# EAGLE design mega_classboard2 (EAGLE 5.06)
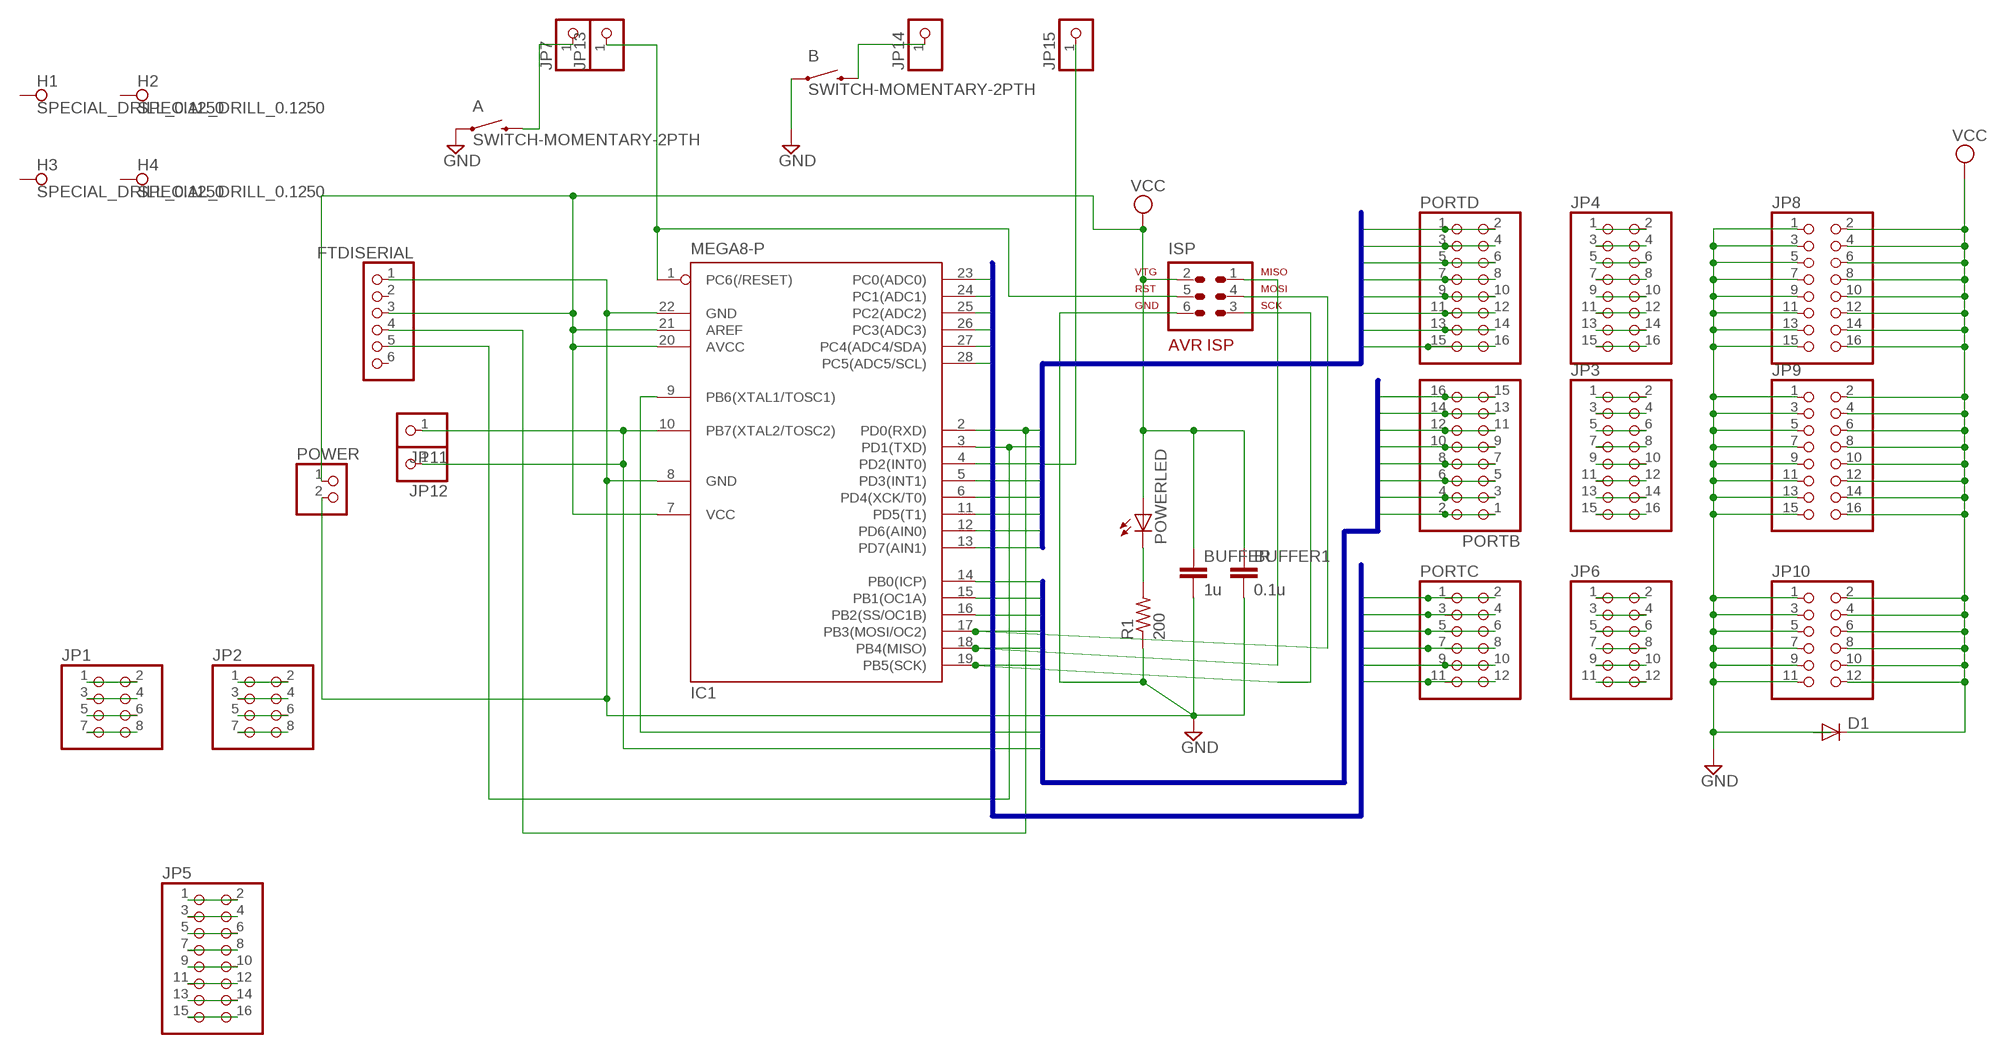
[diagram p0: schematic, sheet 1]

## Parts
A  SWITCH-MOMENTARY-2PTH  [TACTILE-PTH]
B  SWITCH-MOMENTARY-2PTH  [TACTILE-PTH]
BUFFER  1u  C5/3.5  [C5B3.5]
BUFFER1  0.1u  C5/3.5  [C5B3.5]
D1  DIODE1N4148  [DIODE-1N4148]
FTDISERIAL  PINHD-1X6  [1X06]
H1  SPECIAL_DRILL_0.1250  [PAD_0.1250]
H2  SPECIAL_DRILL_0.1250  [PAD_0.1250]
H3  SPECIAL_DRILL_0.1250  [PAD_0.1250]
H4  SPECIAL_DRILL_0.1250  [PAD_0.1250]
IC1  MEGA8-P  [DIL28-3]
ISP  AVR-ISP-6  [AVR-ISP-6]
JP1  PINHD-2X4  [2X04]
JP2  PINHD-2X4  [2X04]
JP3  PINHD-2X8  [2X08]
JP4  PINHD-2X8  [2X08]
JP5  PINHD-2X8  [2X08]
JP6  PINHD-2X6  [2X06]
JP7  PINHD-1X1  [1X01]
JP8  PINHD-2X8  [2X08]
JP9  PINHD-2X8  [2X08]
JP10  PINHD-2X6  [2X06]
JP11  PINHD-1X1  [1X01]
JP12  PINHD-1X1  [1X01]
JP13  PINHD-1X1  [1X01]
JP14  PINHD-1X1  [1X01]
JP15  PINHD-1X1  [1X01]
PORTB  PINHD-2X8  [2X08]
PORTC  PINHD-2X6  [2X06]
PORTD  PINHD-2X8  [2X08]
POWER  PINHD-1X2  [1X02]
POWERLED  LED5MM  [LED5MM]
R1  200  R-US_0204/7  [0204/7]

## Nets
GND: A.1 B.1 BUFFER1.2 BUFFER.2 FTDISERIAL.1 IC1.8(GND) IC1.22(GND) ISP.6 JP8.1 JP8.3 JP8.5 JP8.7 JP8.9 JP8.11 JP8.13 JP8.15 JP9.1 JP9.3 JP9.5 JP9.7 JP9.9 JP9.11 JP9.13 JP9.15 JP10.1 JP10.3 JP10.5 JP10.7 JP10.9 JP10.11 POWER.2 R1.1
N$1: POWERLED.K(C) R1.2
N$2: IC1.1(PC6(/RESET)) ISP.5 JP13.1
N$3: JP6.11 JP6.12
N$4: JP6.9 JP6.10
N$5: JP6.7 JP6.8
N$6: JP6.5 JP6.6
N$7: JP6.3 JP6.4
N$8: JP6.1 JP6.2
N$9: JP3.15 JP3.16
N$10: JP3.13 JP3.14
N$11: JP3.11 JP3.12
N$12: JP3.9 JP3.10
N$13: JP3.7 JP3.8
N$14: JP3.5 JP3.6
N$15: JP3.3 JP3.4
N$16: JP3.1 JP3.2
N$17: JP4.15 JP4.16
N$18: JP4.13 JP4.14
N$19: JP4.11 JP4.12
N$20: JP4.9 JP4.10
N$21: JP4.7 JP4.8
N$22: JP4.5 JP4.6
N$23: JP4.3 JP4.4
N$24: JP4.1 JP4.2
N$25: JP1.1 JP1.2
N$26: JP1.3 JP1.4
N$27: JP1.5 JP1.6
N$28: JP1.7 JP1.8
N$29: JP2.1 JP2.2
N$30: JP2.3 JP2.4
N$31: JP2.5 JP2.6
N$32: JP2.7 JP2.8
N$33: JP5.1 JP5.2
N$34: JP5.3 JP5.4
N$35: JP5.5 JP5.6
N$36: JP5.7 JP5.8
N$37: JP5.9 JP5.10
N$38: JP5.11 JP5.12
N$39: JP5.13 JP5.14
N$40: JP5.15 JP5.16
N$41: B.3 JP14.1
N$46: A.3 JP7.1
PORTB0: IC1.14(PB0(ICP)) PORTB.1 PORTB.2
PORTB1: IC1.15(PB1(OC1A)) PORTB.3 PORTB.4
PORTB2: IC1.16(PB2(SS/OC1B)) PORTB.5 PORTB.6
PORTB3: IC1.17(PB3(MOSI/OC2)) ISP.4 PORTB.7 PORTB.8
PORTB4: IC1.18(PB4(MISO)) ISP.1 PORTB.9 PORTB.10
PORTB5: IC1.19(PB5(SCK)) ISP.3 PORTB.11 PORTB.12
PORTB6: IC1.9(PB6(XTAL1/TOSC1)) PORTB.13 PORTB.14
PORTB7: IC1.10(PB7(XTAL2/TOSC2)) JP11.1 JP12.1 PORTB.15 PORTB.16
PORTC0: IC1.23(PC0(ADC0)) PORTC.1 PORTC.2
PORTC1: IC1.24(PC1(ADC1)) PORTC.3 PORTC.4
PORTC2: IC1.25(PC2(ADC2)) PORTC.5 PORTC.6
PORTC3: IC1.26(PC3(ADC3)) PORTC.7 PORTC.8
PORTC4: IC1.27(PC4(ADC4/SDA)) PORTC.9 PORTC.10
PORTC5: IC1.28(PC5(ADC5/SCL)) PORTC.11 PORTC.12
PORTD0: FTDISERIAL.4 IC1.2(PD0(RXD)) PORTD.1 PORTD.2
PORTD1: FTDISERIAL.5 IC1.3(PD1(TXD)) PORTD.3 PORTD.4
PORTD2: IC1.4(PD2(INT0)) JP15.1 PORTD.5 PORTD.6
PORTD3: IC1.5(PD3(INT1)) PORTD.7 PORTD.8
PORTD4: IC1.6(PD4(XCK/T0)) PORTD.9 PORTD.10
PORTD5: IC1.11(PD5(T1)) PORTD.11 PORTD.12
PORTD6: IC1.12(PD6(AIN0)) PORTD.13 PORTD.14
PORTD7: IC1.13(PD7(AIN1)) PORTD.15 PORTD.16
VCC: BUFFER1.1 BUFFER.1 D1.C FTDISERIAL.3 IC1.7(VCC) IC1.20(AVCC) IC1.21(AREF) ISP.2 JP8.2 JP8.4 JP8.6 JP8.8 JP8.10 JP8.12 JP8.14 JP8.16 JP9.2 JP9.4 JP9.6 JP9.8 JP9.10 JP9.12 JP9.14 JP9.16 JP10.2 JP10.4 JP10.6 JP10.8 JP10.10 JP10.12 POWER.1 POWERLED.A
Unconnected: D1.A FTDISERIAL.2 FTDISERIAL.6 H1.1 H2.1 H3.1 H4.1

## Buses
PORTD[0..7]
PORTB[0..7]
PORTC[0..5]

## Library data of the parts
A B = SparkFun:SWITCH-MOMENTARY-2
BUFFER BUFFER1 = capacitor-wima:C: CAPACITOR
D1 = SparkFun:DIODE: Diode
FTDISERIAL = pinhead:PINHD-1X6: PIN HEADER
H1-H4 = special-drill:SPECIAL_DRILL_: Special drills
IC1 = atmel:MEGA8-P: MICROCONTROLLER 8 Kbytes FLASH, 1 kbytes SRAM, 512 bytes EEPROM, USART, 4-channel 10 bit ADC, 2-channel 8 bit ADC Pin compatible with Atmega48, ATMega88, ATMega168 Source: avr.lbr
ISP = atmel-1:AVR-ISP-6: AVR ISP-6 Serial Programming Header
JP1 JP2 = pinhead:PINHD-2X4: PIN HEADER
JP3-JP5 JP8 JP9 PORTB PORTD = pinhead:PINHD-2X8: PIN HEADER
JP6 JP10 PORTC = pinhead:PINHD-2X6: PIN HEADER
JP7 JP11-JP15 = pinhead:PINHD-1X1: PIN HEADER
POWER = pinhead:PINHD-1X2: PIN HEADER
POWERLED = led:LED: LED
R1 = rcl:R-US_: RESISTOR, American symbol

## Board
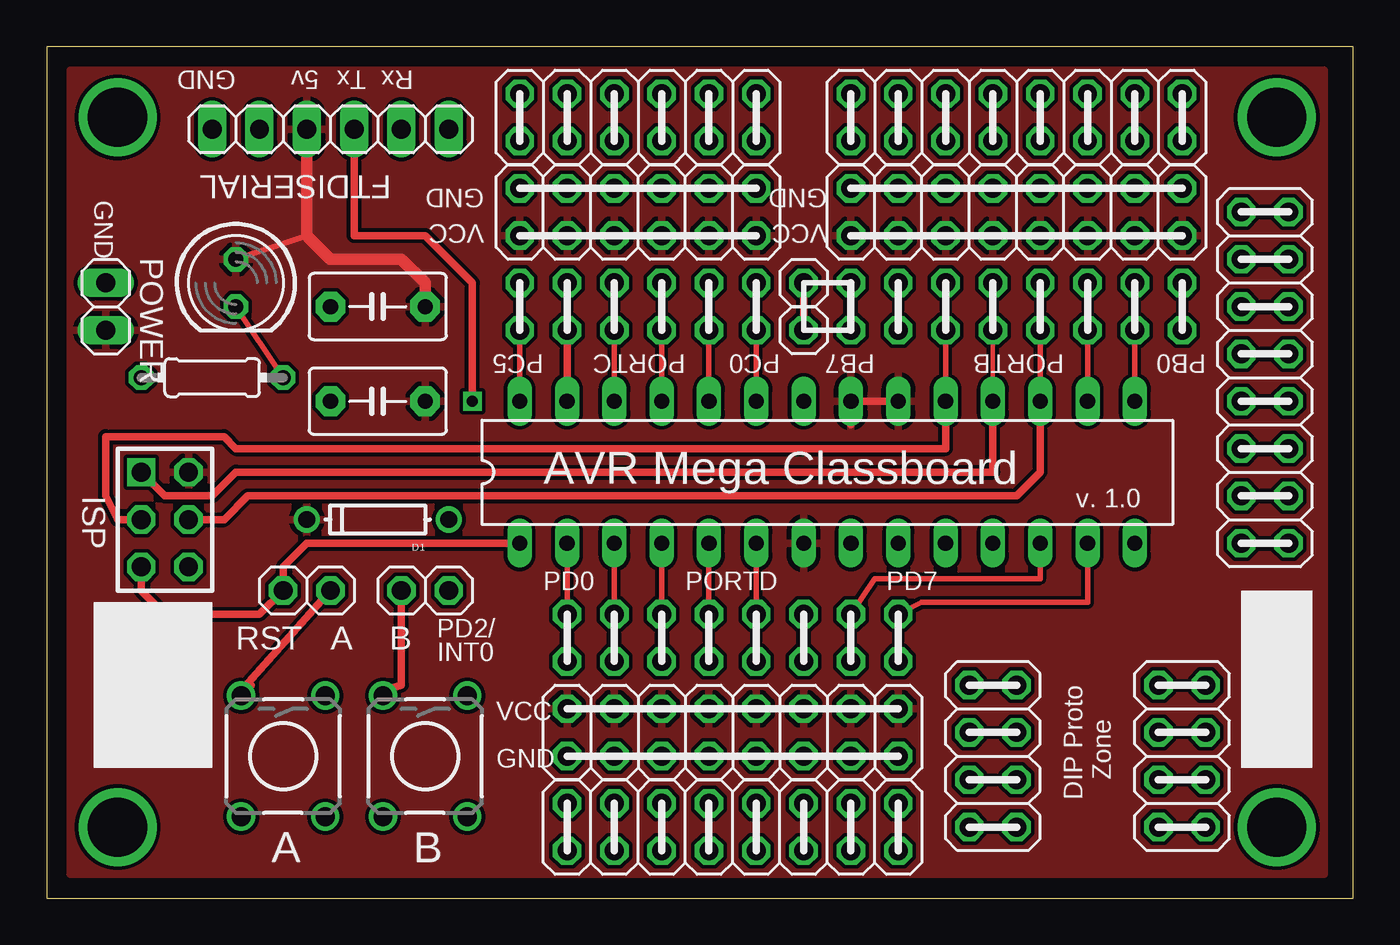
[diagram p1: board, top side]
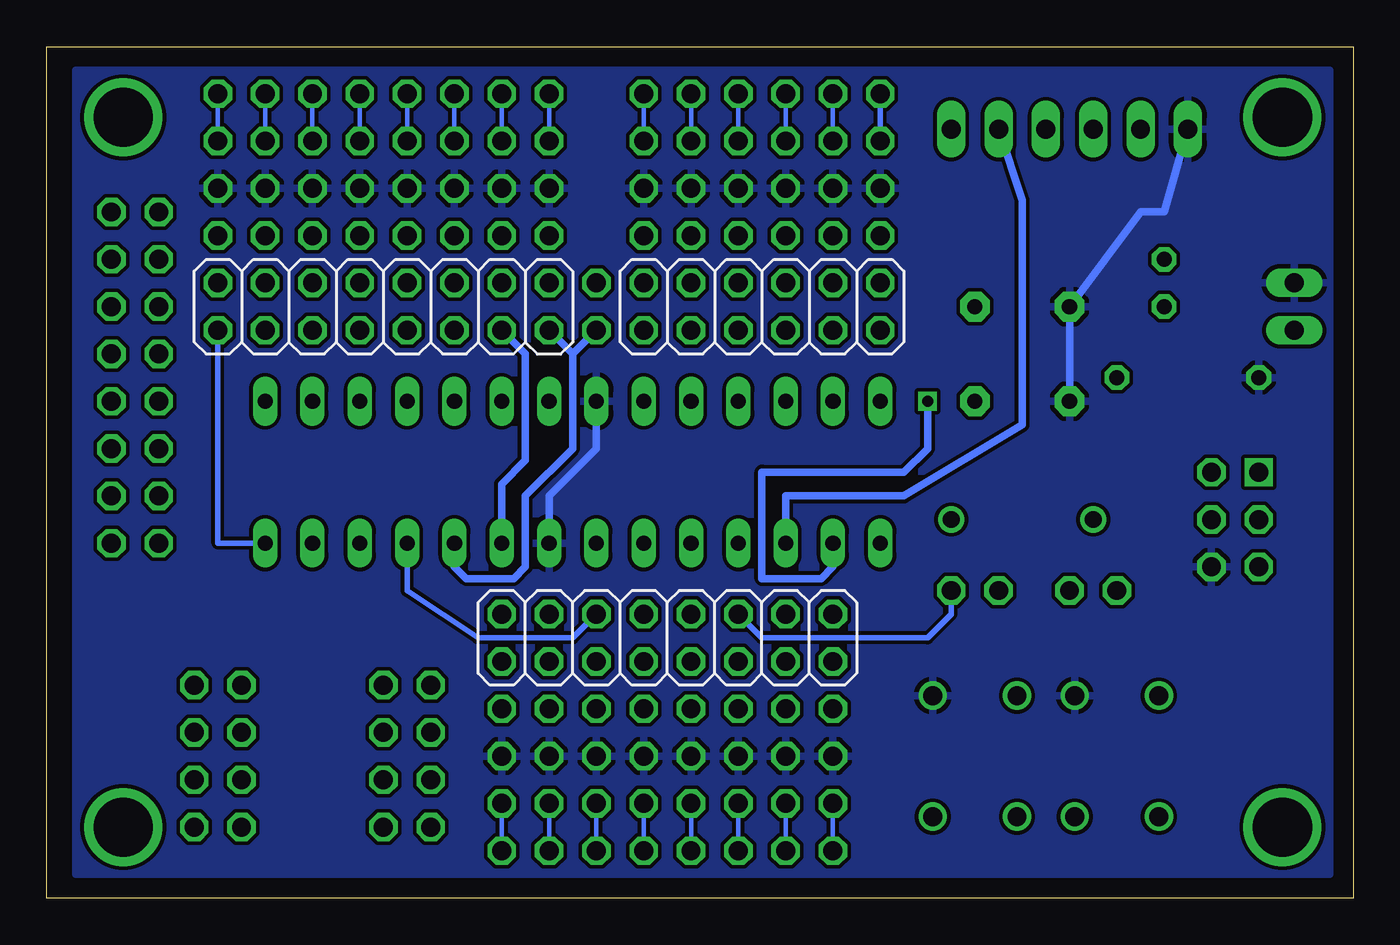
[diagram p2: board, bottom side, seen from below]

Size 70.16 x 45.71 mm. Coordinates in mm from the lower left corner, seen from the top.
Outline: 0,0 70.16,0 70.16,45.71 0,45.71 0,0
Copper layers (1*16): Top 0.035mm / dielectric 1.5mm / Bottom 0.035mm
Design rules "default": minimum track width 10mil, minimum drill 24mil, track to track 8mil, track to pad 8mil, pad to pad 8mil, via to via 8mil, smd to smd 8mil, copper to edge 40mil, drill to drill 8mil, minimum pad ring 10mil, minimum via ring 8mil, stop-mask expansion 4mil, vias tented up to drill 0mil, thermal gap 10mil

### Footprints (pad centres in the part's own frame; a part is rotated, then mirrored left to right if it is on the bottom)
TACTILE-PTH = drill 1.016 round: 1 -3.251,2.261; 2 3.251,2.261; 3 -3.251,-2.261; 4 3.251,-2.261
C5B3.5 = drill 0.813 pad 1.6 octagon: 1 -2.54,0; 2 2.54,0
DIODE-1N4148 = drill 0.9 round: A -3.81,0; C 3.81,0
1X06 = drill 1.016 long: 1 -6.35,0; 2 -3.81,0; 3 -1.27,0; 4 1.27,0; 5 3.81,0; 6 6.35,0
PAD_0.1250 = drill 3.175 pad 3.175 round: 1 0,0
DIL28-3 = drill 0.813 long: 1 -16.51,-3.81; 2 -13.97,-3.81; 3 -11.43,-3.81; 4 -8.89,-3.81; 5 -6.35,-3.81; 6 -3.81,-3.81; 7 -1.27,-3.81; 8 1.27,-3.81; 9 3.81,-3.81; 10 6.35,-3.81; 11 8.89,-3.81; 12 11.43,-3.81; 13 13.97,-3.81; 14 16.51,-3.81; 15 16.51,3.81; 16 13.97,3.81; 17 11.43,3.81; 18 8.89,3.81; 19 6.35,3.81; 20 3.81,3.81; 21 1.27,3.81; 22 -1.27,3.81; 23 -3.81,3.81; 24 -6.35,3.81; 25 -8.89,3.81; 26 -11.43,3.81; 27 -13.97,3.81; 28 -16.51,3.81
AVR-ISP-6 = drill 1.016 square: 1 -2.54,-1.27 | drill 1.016 octagon: 2 -2.54,1.27; 3 0,-1.27; 4 0,1.27; 5 2.54,-1.27; 6 2.54,1.27
2X04 = drill 1.016 octagon: 1 -3.81,-1.27; 2 -3.81,1.27; 3 -1.27,-1.27; 4 -1.27,1.27; 5 1.27,-1.27; 6 1.27,1.27; 7 3.81,-1.27; 8 3.81,1.27
2X08 = drill 1.016 octagon: 1 -8.89,-1.27; 2 -8.89,1.27; 3 -6.35,-1.27; 4 -6.35,1.27; 5 -3.81,-1.27; 6 -3.81,1.27; 7 -1.27,-1.27; 8 -1.27,1.27; 9 1.27,-1.27; 10 1.27,1.27; 11 3.81,-1.27; 12 3.81,1.27; 13 6.35,-1.27; 14 6.35,1.27; 15 8.89,-1.27; 16 8.89,1.27
2X06 = drill 1.016 octagon: 1 -6.35,-1.27; 2 -6.35,1.27; 3 -3.81,-1.27; 4 -3.81,1.27; 5 -1.27,-1.27; 6 -1.27,1.27; 7 1.27,-1.27; 8 1.27,1.27; 9 3.81,-1.27; 10 3.81,1.27; 11 6.35,-1.27; 12 6.35,1.27
1X01 = drill 1.016 octagon: 1 0,0
1X02 = drill 1.016 long: 1 -1.27,0; 2 1.27,0
LED5MM = drill 0.813 octagon: A -1.27,0; K 1.27,0
0204/7 = drill 0.813 octagon: 1 -3.81,0; 2 3.81,0

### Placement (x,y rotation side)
A  12.7,7.62 270 top
B  20.32,7.62 270 top
BUFFER  17.78,26.67 180 top
BUFFER1  17.78,31.75 180 top
D1  17.78,20.32 180 top
FTDISERIAL  15.24,41.27 0 top
H1  3.81,41.91 0 top
H2  3.81,3.81 0 top
H3  66.04,41.91 0 top
H4  66.04,3.81 0 top
IC1  41.91,22.86 0 top
ISP  6.35,20.32 270 top
JP1  50.8,7.62 90 top
JP2  60.96,7.62 90 top
JP3  52.07,41.91 0 top
JP4  36.83,3.81 180 top
JP5  65.41,27.94 90 top
JP6  31.75,41.91 0 top
JP7  15.24,16.51 0 top
JP8  52.07,36.83 180 top
JP9  36.83,8.89 0 top
JP10  31.75,36.83 180 top
JP11  40.64,30.48 0 top
JP12  40.64,33.02 0 top
JP13  12.7,16.51 0 top
JP14  19.05,16.51 0 top
JP15  21.59,16.51 0 top
PORTB  52.07,31.75 0 bottom
PORTC  31.75,31.75 0 bottom
PORTD  36.83,13.97 180 bottom
POWER  3.18,31.75 90 top
POWERLED  10.16,33.02 270 top
R1  8.89,27.94 0 top

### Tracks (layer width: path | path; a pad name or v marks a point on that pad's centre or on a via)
GND
  Bottom 0.406: IC1.8 43.18,21.59 40.64,24.13 IC1.22 | BUFFER.2 BUFFER1.2 11.43,36.83 10.16,36.83 FTDISERIAL.1
  pour Bottom: 1.27,44.45 1.27,1.27 68.58,1.27 68.58,44.45
N$1
  Top 0.305: R1.2 POWERLED.K
N$2
  Top 0.406: ISP.5 5.08,16.51 6.35,15.24 11.43,15.24 JP13.1 12.7,17.78 13.97,19.05 IC1.1
N$3
  Bottom 0.254: JP6.11 JP6.12
N$4
  Bottom 0.254: JP6.9 JP6.10
N$5
  Bottom 0.254: JP6.7 JP6.8
N$6
  Bottom 0.254: JP6.5 JP6.6
N$7
  Bottom 0.254: JP6.3 JP6.4
N$8
  Bottom 0.305: JP6.1 JP6.2
N$9
  Bottom 0.254: JP3.15 JP3.16
N$10
  Bottom 0.254: JP3.13 JP3.14
N$11
  Bottom 0.254: JP3.11 JP3.12
N$12
  Bottom 0.254: JP3.9 JP3.10
N$13
  Bottom 0.254: JP3.7 JP3.8
N$14
  Bottom 0.254: JP3.5 JP3.6
N$15
  Bottom 0.254: JP3.3 JP3.4
N$16
  Bottom 0.254: JP3.1 JP3.2
N$17
  Bottom 0.254: JP4.16 JP4.15
N$18
  Bottom 0.254: JP4.14 JP4.13
N$19
  Bottom 0.254: JP4.12 JP4.11
N$20
  Bottom 0.254: JP4.10 JP4.9
N$21
  Bottom 0.254: JP4.8 JP4.7
N$22
  Bottom 0.254: JP4.6 JP4.5
N$23
  Bottom 0.254: JP4.4 JP4.3
N$24
  Bottom 0.254: JP4.2 JP4.1
N$25
  Top 0.305: JP1.2 JP1.1
N$26
  Top 0.305: JP1.4 JP1.3
N$27
  Top 0.305: JP1.6 JP1.5
N$28
  Top 0.305: JP1.8 JP1.7
N$29
  Top 0.305: JP2.2 JP2.1
N$30
  Top 0.305: JP2.4 JP2.3
N$31
  Top 0.305: JP2.6 JP2.5
N$32
  Top 0.305: JP2.8 JP2.7
N$33
  Top 0.406: JP5.2 JP5.1
N$34
  Top 0.406: JP5.4 JP5.3
N$35
  Top 0.406: JP5.6 JP5.5
N$36
  Top 0.406: JP5.8 JP5.7
N$37
  Top 0.406: JP5.10 JP5.9
N$38
  Top 0.406: JP5.12 JP5.11
N$39
  Top 0.406: JP5.14 JP5.13
N$40
  Top 0.406: JP5.16 JP5.15
N$41
  Top 0.406: JP14.1 19.05,11.43 18.41,11.23 B.3
N$46
  Top 0.406: JP7.1 10.16,10.79 11,11.43 A.3
PORTB0
  Top 0.254: PORTB.1 PORTB.2
  Bottom 0.305: IC1.14 60.96,19.05 PORTB.1
PORTB1
  Top 0.305: IC1.15 PORTB.3 PORTB.4
PORTB2
  Top 0.254: PORTB.5 PORTB.6
  Top 0.305: IC1.16 PORTB.5
PORTB3
  Top 0.254: PORTB.7 PORTB.8
  Top 0.305: IC1.17 PORTB.7
  Top 0.406: ISP.4 9.52,20.32 10.8,21.59 52.07,21.59 53.34,22.86 IC1.17
PORTB4
  Top 0.254: IC1.18 PORTB.9 PORTB.10
  Top 0.406: IC1.18 50.8,22.86 10.16,22.86 8.89,21.59 6.35,21.59 ISP.1
PORTB5
  Top 0.254: PORTB.11 PORTB.12
  Top 0.305: IC1.19 PORTB.11
  Top 0.406: ISP.3 3.81,20.32 3.18,21.59 3.18,24.77 9.52,24.77 10.16,24.13 48.26,24.13 IC1.19
PORTB6
  Top 0.254: PORTB.13 PORTB.14
  Bottom 0.406: PORTB.13 44.45,29.21 44.45,23.49 45.72,22.23 IC1.9
PORTB7
  Top 0.406: PORTB.15 PORTB.16 | JP11.1 JP12.1
  Bottom 0.406: 41.91,29.21 PORTB.15 | 41.91,29.21 41.91,24.13 44.45,21.59 44.45,17.78 45.09,17.14 47.62,17.14 48.26,17.78 IC1.10 | 41.91,29.21 JP11.1
PORTC0
  Top 0.254: PORTC.1 PORTC.2
  Top 0.305: IC1.23 PORTC.1
PORTC1
  Top 0.254: PORTC.3 PORTC.4
  Top 0.305: IC1.24 PORTC.3
PORTC2
  Top 0.254: PORTC.5 PORTC.6
  Top 0.305: IC1.25 PORTC.5
PORTC3
  Top 0.254: PORTC.7 PORTC.8
  Top 0.305: IC1.26 PORTC.7
PORTC4
  Top 0.254: PORTC.9 PORTC.10
  Top 0.406: IC1.27 PORTC.9
PORTC5
  Top 0.305: IC1.28 PORTC.11 PORTC.12
PORTD0  (via drill 0.6)
  Top 0.305: PORTD.1 IC1.2
  Top 0.406: PORTD.2 PORTD.1 | FTDISERIAL.4 16.51,35.56 20.32,35.56 22.86,33.02 v22.86,26.67
  Bottom 0.406: v22.86,26.67 22.86,24.13 24.13,22.86 31.75,22.86 31.75,17.14 28.58,17.14 27.94,17.78 IC1.2
PORTD1
  Top 0.305: PORTD.3 IC1.3
  Top 0.406: PORTD.4 PORTD.3
  Bottom 0.406: FTDISERIAL.5 17.78,37.46 17.78,25.4 24.13,21.59 30.48,21.59 IC1.3
PORTD2
  Top 0.305: PORTD.5 IC1.4
  Top 0.406: PORTD.5 PORTD.6
  Bottom 0.305: JP15.1 21.59,15.24 22.86,13.97 31.75,13.97 PORTD.5
PORTD3
  Top 0.254: PORTD.8 PORTD.7
  Top 0.305: PORTD.7 IC1.5
PORTD4
  Top 0.254: PORTD.10 PORTD.9
  Top 0.305: PORTD.9 IC1.6
PORTD5
  Top 0.406: PORTD.12 PORTD.11
  Bottom 0.305: IC1.11 50.8,16.51 46.99,13.97 41.91,13.97 PORTD.11
PORTD6
  Top 0.254: PORTD.14 PORTD.13
  Top 0.305: IC1.12 53.34,17.14 44.45,17.14 PORTD.13
PORTD7
  Top 0.254: PORTD.16 PORTD.15
  Top 0.305: IC1.13 55.88,15.87 46.99,15.87 PORTD.15
VCC
  Top 0.305: POWERLED.A 13.97,35.56
  Top 0.406: IC1.20 IC1.21 43.18,25.4
  Top 0.61: BUFFER1.1 20.32,33.02 19.05,34.29 15.24,34.29 13.97,35.56 FTDISERIAL.3
  pour Top: 1.27,44.45 1.27,1.27 68.58,1.27 68.58,44.45

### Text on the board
tNames: GND | 5v | Tx | Rx | GND | GND | GND | VCC | VCC | PC5 | PC0 | PB7 | PB0 | AVR Mega Classboard | v. 1.0 | PD0 | PD7 | RST | A | B | PD2/ | INT0 | DIP Proto | VCC | GND | Zone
